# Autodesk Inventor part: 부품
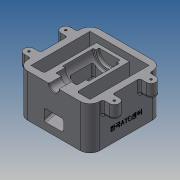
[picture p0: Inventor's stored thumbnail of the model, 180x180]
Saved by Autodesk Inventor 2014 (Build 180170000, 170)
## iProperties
Created: 2018-01
Part Number: 부품
Material: 일반
Document SubType Name: Modeling
Designer: 601-26
Density: 1 g/cm^3
Appearance: 기본값
Author: 601-26
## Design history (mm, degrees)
sketch "스케치1"
  geometry: L1 (55, -55)-(-55, -55); L2 (-55, -55)-(-55, 55); L3 (-55, 55)-(55, 55); L4 (55, 55)-(55, -55); L5 (55, -55)-(-55, 55); L6 (-55, -55)-(55, 55); 1 further point
  constraints: 12 end point, 2 midpoint, 2 parallel, 1 horizontal, 1 perpendicular
  dimensions: "d0" = 110 distance of L1.start L1.end; "d1" = 110 distance of L3.end L1.start
extrude "돌출1" new body sketch "스케치1" distance "d2" = 65; taper "d3" = 0 deg
sketch "스케치2"
  geometry: L1 (-55, -55)-(55, -55) reference; L2 (55, -55)-(55, 55) reference; L3 (55, 55)-(-55, 55) reference; L4 (-55, 55)-(-55, -55) reference; L5 (-45, 55)-(-45, 45); L6 (-55, 45)-(-45, 45); L7 (-55, 0)-(55, 0); L8 (-55, 25)-(-45, 25); L9 (-55, -25)-(-45, -25); L10 (45, 45)-(55, 45); L11 (-55, -45)-(-45, -45); L12 (45, -45)-(55, -45); L13 (45, 25)-(55, 25); L14 (45, -25)-(55, -25); L15 (-45, 25)-(35, 25); L16 (-45, 45)-(45, 45); L17 (-45, -25)-(35, -25); L18 (-45, -45)-(45, -45); L19 (55, 45)-(55, -45); L20 (-45, 45)-(-45, 25); L21 (-45, -45)-(-45, -55); L22 (-45, -25)-(-45, -45); L23 (-45, 25)-(-45, -25); L24 (35, 55)-(35, 45); L25 (35, 45)-(35, 25); L26 (35, -45)-(35, -55); L27 (35, 25)-(45, 25); L28 (35, -25)-(45, -25); L29 (35, 25)-(35, -25); L30 (35, -25)-(35, -45); L31 (45, 45)-(45, -45); 1 further point
  constraints: 54 end point, 16 perpendicular, 14 point on line, 9 parallel, 2 midpoint, 1 collinear, 1 other
  dimensions: "d4" = 10 distance between parallel lines of L4 L5; "d5" = 10 distance between parallel lines of L6 L3; "d6" = 50 distance between parallel lines of L9 L8; "d8" = 10 distance between parallel lines of L1 L11; "d9" = 20 distance between parallel lines of L19 L24; "d10" = 10 distance between parallel lines of L2 L31
extrude "돌출2" cut sketch "스케치2" distance "d11" = 110; taper "d12" = 0 deg
sketch "스케치4"
  geometry: L1 (-45, -25)-(35, -25) reference; L2 (35, -25)-(35, 25) reference; L3 (-55, 55)-(-55, -55) reference; L4 (35, 0)-(-55, 0); L5 (30, 0)-(30, -16); L6 (25, 0)-(25, -20); L7 (35, -20)-(25, -20); L8 (-22, 0)-(-22, -16); L9 (35, -16)-(30, -16); L10 (-36, -20)-(-36, -16); L11 (-55, -7.5)-(-36, -7.5); L12 (-36, -16)-(-55, -16); L13 (-36, -16)-(-36, 0); L14 (-22, -16)-(-22, -20); L15 (-22, -20)-(-55, -20); L16 (25, -16)-(-22, -16); L17 (-22, -16)-(-36, -16); L18 (25, -20)-(-22, -20); L19 (30, -16)-(30, -20); L20 (30, -16)-(25, -16); 1 further point
  constraints: 34 end point, 14 perpendicular, 14 point on line, 4 parallel, 3 midpoint
  dimensions: "d13" = 5 distance between parallel lines of L2 L5; "d14" = 5 distance between parallel lines of L6 L5; "d15" = 40 diameter of L7 L4; "d16" = 47 distance between parallel lines of L6 L8; "d17" = 32 diameter of L9 L4; "d18" = 14 distance between parallel lines of L8 L10; "d19" = 15 diameter of L11 L4
revolve "회전1" sketch "스케치4" stored, may be unused: angle "d20" = 90 deg
sketch "스케치8"
  geometry: L1 (80, -65)-(0, -65) reference; L2 (0, 0)-(80, 0) reference; L3 (0, 0)-(0, -65) reference; L4 (-10, -65)-(-10, 0) reference; L5 (-10, -35)-(90.247, -35); L6 (80, 0)-(80, -65); L7 (-10, -65)-(100, -65) reference; L8 (100, -65)-(100, 0) reference; L9 (80, 0)-(80, -65) reference; L10 (80, -35)-(0, -56.436); 1 further point
  constraints: 6 end point, 6 point on line, 2 perpendicular
  dimensions: "d44" = 30 distance between parallel lines of L1 L5; "d45" = 20 distance between parallel lines of L8 L6; "d46" = 105 deg angle of L3 L10
extrude "돌출4" cut sketch "스케치8" stored distance "d47" = 30; taper "d48" = 0 deg
sketch "스케치10"
  geometry: L1 (-25, 65)-(22, 65) reference; L2 (-25, 65)-(-25, 65) reference; L3 (22, 65)-(-25, 65) reference; L4 (22, 65)-(22, 65) reference; L5 (-35, 30)-(45, 8.564) reference; L6 (45, 65)-(45, 8.564) reference; L7 (-35, 65)-(45, 65) reference; L8 (-35, 65)-(-35, 30) reference; L9 (55, 11.061)-(-20, 31.157); L10 (55, 0)-(55, 65) reference; L11 (55, 29.061)-(17, 39.243); L12 (22, 45)-(-25, 45) reference; L13 (17, 54.243)-(-20, 54.243); L14 (17, 54.243)-(17, 39.243); L15 (-20, 54.243)-(-20, 31.157); 3 further points
  constraints: 10 end point, 2 midpoint, 2 parallel, 2 point on line, 1 perpendicular, 1 vertical alignment
  dimensions: "d55" = 5 distance between parallel lines of L5 L9; "d56" = 18 distance of L9.start L11.start; "d57" = 75 deg angle of L10 L11; "d58" = 105 deg angle of L10 L9 (derived); "d59" = 37 distance of L13.start L13.end; "d60" = 15 distance of L13.start L11.end
extrude "돌출5" cut sketch "스케치10" stored distance "d61" = 30; taper "d62" = 0 deg
sketch "스케치11"
  geometry: L1 (55, 55)-(-55, 55) reference; L2 (-55, 55)-(-55, 7.5) reference; L3 (35, 25)-(-45, 25) reference; L4 (55, 65)-(-55, 65); L5 (-28, 55)-(-28, 75); L6 (-20.5, 65)-(-20.5, 55); L7 (-35.5, 65)-(-35.5, 55); L8 (-55, 55)-(55, 55) reference; L9 (-35.5, 55)-(-20.5, 55); A1 r 7.5 centre (-28, 65) between (-20.5, 65) and (-35.5, 65); 1 further point
  constraints: 10 end point, 6 point on line, 3 perpendicular, 2 point on circle, 2 tangent, 1 centre point, 1 collinear, 1 midpoint, 1 parallel
  dimensions: "d66" = 10 distance between parallel lines of L1 L4; "d67" = 27 distance between parallel lines of L2 L5; "d68" = 15 diameter of A1
extrude "돌출6" join sketch "스케치11" distance "d69" = 20; taper "d70" = 0 deg
sketch "스케치12"
  geometry: A1 r 7.5 centre (-28, 65) between (-20.5, 65) and (-35.5, 65) reference; 2 further points
  constraints: 1 coincident
hole "구멍1" sketch "스케치12" at (-28, 65) diameter "d71" = 3.242; stored, may be unused: countersink angle "d75" = 82 deg, drill point angle "d77" = 118 deg; dims "d72" = 9, "d73" = 3.023, "d74" = 2, "d76" = 11
fillet "모깎기1" dims "d78" = 15
sketch "스케치13"
  geometry: L1 (-34.5, 0)-(-34.5, -65) reference; 2 further points
  constraints: 1 other
  dimensions: "d79" = 20 distance of point (20.5, -65) point (20.5, -45); "d80" = 55 distance from line of L1 point (20.5, -45)
extrude "돌출7" join sketch "스케치13" distance "d81" = 0.5; taper "d82" = 0 deg
fillet "모깎기2" dims "d83" = 1
fillet "모깎기3" dims "d84" = 3
fillet "모깎기4" dims "d85" = 3
fillet "모깎기5" dims "d86" = 3
fillet "모깎기6" dims "d87" = 3
fillet "모깎기7" dims "d88" = 3
chamfer "모따기1" distance "d89" = 1; stored, may be unused: second distance "d90" = 2, angle "d91" = 45 deg
node "솔리드1"
mirror "대칭1"
mirror "대칭2"
mirror "대칭3"
mirror "대칭4"
node "투영된 루프11"
node "투영된 루프12"
